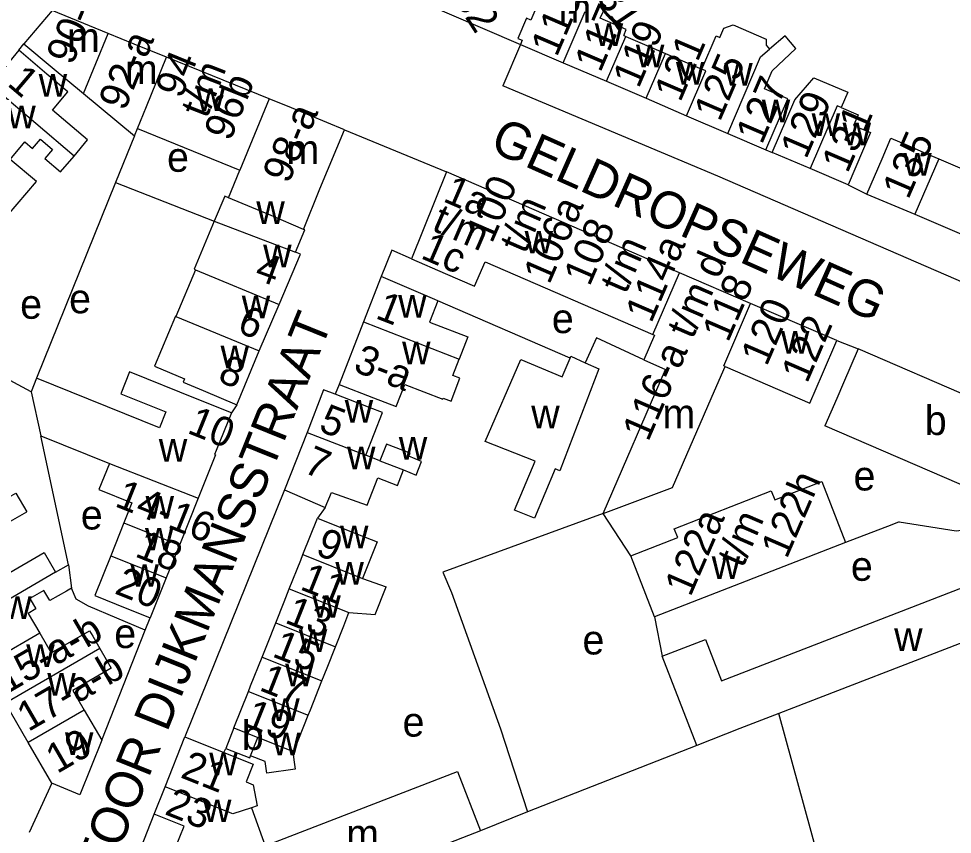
# Model space of a CAD drawing. Extents: x 161141 to 163125, y 381621 to 383200.
# Drawn here: x 162150.7 to 162277.6, y 382532 to 382642.8 of the extents above; entities that cross this region are included whole.
import ezdxf

# ---------------------------------------------------------------- set-up
doc = ezdxf.new("R2010")
doc.units = 0
for name, color, linetype in [('BLT_Basislijn', 7, 'Continuous'), ('BLT_Bebouwing', 7, 'Continuous'), ('BLT_Centroide', 7, 'Continuous'), ('BLT_Huisnummer', 7, 'Continuous'), ('BLT_Huisnummer_ tussenligend', 7, 'Continuous'), ('BLT_Huisnummer_reeks', 7, 'Continuous'), ('BLT_Onderverdeling_panden', 7, 'Continuous'), ('BLT_Straatnaam', 7, 'Continuous'), ('BLT_Vlakafsluiter', 7, 'Continuous')]:
    doc.layers.add(name, color=color, linetype=linetype)

msp = doc.modelspace()

# ---------------------------------------------------------------- linework, layer by layer
at = {"layer": 'BLT_Basislijn'}
for p, q in [((162150.75, 382638.48), (162151.43, 382639.36)), ((162218.92, 382639.28), (162216.51, 382633.67)), ((162166.46, 382626.88), (162163.9, 382620.53)), ((162252.26, 382624.97), (162253.12, 382624.62)), ((162163.9, 382620.53), (162153.17, 382593.92)), ((162163.9, 382620.53), (162177.31, 382615.28)), ((162263.41, 382620.2), (162265.95, 382618.96)), ((162261.9, 382599.06), (162264.79, 382597.91)), ((162194.26, 382593.1), (162193.71, 382591.77)), ((162180.39, 382590.32), (162179.64, 382589.24)), ((162157.52, 382568.57), (162153.72, 382586.1)), ((162186.87, 382578.76), (162173.32, 382545.19)), ((162192.38, 382576.39), (162191.32, 382574.93)), ((162233.91, 382569.8), (162230.16, 382575.56)), ((162270.38, 382574.4), (162269.36, 382574.02)), ((162269.36, 382574.02), (162263.07, 382571.62)), ((162167.92, 382559.68), (162168.6, 382561.4)), ((162237.14, 382561.53), (162238.16, 382556.17)), ((162162.02, 382544.74), (162167.92, 382559.68)), ((162260.76, 382523.75), (162254, 382548.36)), ((162242.85, 382544.04), (162219.85, 382535)), ((162178.61, 382543.09), (162178.88, 382543.64)), ((162155.22, 382538.91), (162152.16, 382532.22)), ((162219.85, 382535), (162213.46, 382532.44))]:
    msp.add_line(p, q, dxfattribs=at)
for points in [[(162377.15, 382570.34), (162374.71, 382570.72), (162341.47, 382580.52), (162303.7, 382596.26), (162245.74, 382621.4), (162216.51, 382633.67)], [(162204.09, 382610.15), (162201.43, 382611.31), (162199.96, 382607.76)], [(162225.64, 382596.66), (162207.69, 382604.46)], [(162235.65, 382596.41), (162229.24, 382599.4), (162227.72, 382596.04)], [(162152.43, 382592.09), (162143.75, 382596.76), (162138.41, 382593.73)], [(162270.38, 382574.4), (162278.09, 382573.22), (162281.73, 382573.67), (162282.87, 382574.53), (162284.03, 382577.2)], [(162230.16, 382575.56), (162208.38, 382567.57), (162209.55, 382564.84), (162216.18, 382546.3), (162219.85, 382535)], [(162167.92, 382559.68), (162160.23, 382562.96), (162158.56, 382563.92), (162157.9, 382565.43)]]:
    msp.add_lwpolyline(points, dxfattribs=at)
at = {"layer": 'BLT_Bebouwing'}
for p, q in [((162155.26, 382643.89), (162151.43, 382639.36)), ((162162.87, 382640.78), (162155.26, 382643.89)), ((162166.4, 382639.34), (162162.87, 382640.78)), ((162232.93, 382640.49), (162233.21, 382640.37)), ((162233.21, 382640.37), (162238.59, 382638.06)), ((162170.81, 382637.55), (162166.4, 382639.34)), ((162218.92, 382639.28), (162224.72, 382636.79)), ((162150.75, 382638.48), (162146.81, 382633.83)), ((162238.59, 382638.06), (162243.56, 382635.93)), ((162184.76, 382631.9), (162170.81, 382637.55)), ((162224.72, 382636.79), (162230.59, 382634.27)), ((162230.59, 382634.27), (162235.97, 382631.96)), ((162159.55, 382632.63), (162166.46, 382626.88)), ((162187.8, 382630.65), (162184.76, 382631.9)), ((162235.97, 382631.96), (162241.48, 382629.59)), ((162194.98, 382627.7), (162187.8, 382630.65)), ((162241.48, 382629.59), (162247.06, 382627.2)), ((162166.46, 382626.88), (162166.86, 382627.87)), ((162191.67, 382619.65), (162194.98, 382627.7)), ((162247.06, 382627.2), (162252.26, 382624.97)), ((162258.27, 382622.41), (162253.12, 382624.62)), ((162275.73, 382623.74), (162282.08, 382621.01)), ((162179.23, 382618.46), (162180.77, 382622.2)), ((162208.85, 382621.96), (162204.09, 382610.15)), ((162240.52, 382608.24), (162208.85, 382621.96)), ((162263.41, 382620.2), (162258.27, 382622.41)), ((162189.41, 382614.16), (162191.67, 382619.65)), ((162265.95, 382618.96), (162272.48, 382616.2)), ((162272.48, 382616.2), (162278.85, 382613.51)), ((162174.76, 382608.68), (162172.09, 382602.33)), ((162199.96, 382607.76), (162197.56, 382601.59)), ((162250.18, 382604.08), (162240.52, 382608.24)), ((162183.4, 382597.64), (162186.12, 382603.97)), ((162261.9, 382599.06), (162250.18, 382604.08)), ((162197.56, 382601.59), (162194.26, 382593.1)), ((162180.39, 382590.32), (162183.4, 382597.64)), ((162288.54, 382587.63), (162264.79, 382597.91)), ((162235.65, 382596.41), (162238.62, 382595.12)), ((162230.16, 382575.56), (162238.62, 382595.12)), ((162245.28, 382592.24), (162246.71, 382595.54)), ((162246.71, 382595.54), (162258.22, 382590.55)), ((162153.17, 382593.92), (162152.43, 382592.09)), ((162169.86, 382587.21), (162153.17, 382593.92)), ((162239.56, 382579.07), (162245.28, 382592.24)), ((162152.43, 382592.09), (162153.72, 382586.1)), ((162179.64, 382589.24), (162177.58, 382584.11)), ((162284.03, 382577.2), (162260.27, 382587.47)), ((162153.72, 382586.1), (162163.06, 382582.34)), ((162189.91, 382586.57), (162186.87, 382578.76)), ((162186.87, 382578.76), (162192.38, 382576.39)), ((162230.16, 382575.56), (162239.56, 382579.07)), ((162175.12, 382577.62), (162172.56, 382571.27)), ((162148.68, 382573.96), (162151.82, 382575.78)), ((162189.35, 382569.97), (162191.32, 382574.93)), ((162165.03, 382574.3), (162163.23, 382569.82)), ((162172.56, 382571.27), (162170.77, 382566.79)), ((162263.07, 382571.62), (162237.14, 382561.53)), ((162148.98, 382567.24), (162154.19, 382570.26)), ((162154.19, 382570.26), (162155.75, 382567.56)), ((162189.05, 382569.23), (162189.35, 382569.97)), ((162237.14, 382561.53), (162233.91, 382569.8)), ((162155.75, 382567.56), (162157.52, 382568.57)), ((162157.52, 382568.57), (162157.9, 382565.43)), ((162187.5, 382565.32), (162189.05, 382569.23)), ((162170.77, 382566.79), (162168.6, 382561.4)), ((162246.2, 382552.82), (162282.68, 382566.95)), ((162197.46, 382566.74), (162200.68, 382565.57)), ((162186.79, 382563.53), (162187.5, 382565.32)), ((162185.65, 382560.68), (162186.79, 382563.53)), ((162194.9, 382560.3), (162195.61, 382562.1)), ((162184.52, 382557.83), (162185.65, 382560.68)), ((162285.2, 382560.44), (162254, 382548.36)), ((162193.76, 382557.45), (162194.9, 382560.3)), ((162238.16, 382556.17), (162244.03, 382558.44)), ((162244.03, 382558.44), (162246.2, 382552.82)), ((162183.8, 382556.03), (162184.52, 382557.83)), ((162192.63, 382554.6), (162193.76, 382557.45)), ((162182.25, 382552.13), (162183.8, 382556.03)), ((162242.85, 382544.04), (162238.16, 382556.17)), ((162191.92, 382552.8), (162192.63, 382554.6)), ((162190.36, 382548.9), (162191.92, 382552.8)), ((162181.96, 382551.39), (162182.25, 382552.13)), ((162179.98, 382546.43), (162181.96, 382551.39)), ((162152.02, 382544.43), (162148.93, 382549.77)), ((162159.64, 382548.85), (162162.02, 382544.74)), ((162190.07, 382548.16), (162190.36, 382548.9)), ((162254, 382548.36), (162248.72, 382546.32)), ((162170.63, 382538.43), (162173.32, 382545.19)), ((162173.32, 382545.19), (162178.61, 382543.09)), ((162248.72, 382546.32), (162242.85, 382544.04)), ((162155.22, 382538.91), (162152.02, 382544.43)), ((162178.61, 382543.09), (162182.61, 382541.5)), ((162169.14, 382534.69), (162170.63, 382538.43)), ((162165.28, 382524.99), (162169.14, 382534.69))]:
    msp.add_line(p, q, dxfattribs=at)
for points in [[(162221.87, 382646.21), (162220.32, 382642.6), (162219.72, 382642.85), (162218.54, 382640.1), (162219.16, 382639.84), (162218.92, 382639.28)], [(162232.93, 382640.49), (162233.27, 382641.32), (162229.74, 382642.83), (162230.49, 382644.49), (162229.91, 382644.87)], [(162246, 382640.21), (162246.54, 382641.47), (162247.79, 382641.95), (162252.31, 382640.01), (162252.28, 382639.18), (162252.75, 382638.63)], [(162243.56, 382635.93), (162245.49, 382640.43), (162246, 382640.21)], [(162252.26, 382624.97), (162254.23, 382629.56), (162255.22, 382631.89), (162252.05, 382633.24), (162253.1, 382635.69), (162256.33, 382638.73), (162254.89, 382640.44), (162252.75, 382638.63)], [(162151.43, 382639.36), (162155.28, 382636.17), (162159.55, 382632.63)], [(162158.25, 382624.12), (162160.09, 382626.3), (162155.33, 382630.34), (162157.43, 382632.82), (162154.55, 382635.26), (162150.75, 382638.48)], [(162253.12, 382624.62), (162255.09, 382629.22), (162256.18, 382631.75), (162258.75, 382634.76), (162263.38, 382632.78), (162262.49, 382630.71)], [(162262.49, 382630.71), (162264.78, 382629.73), (162264.15, 382628.27), (162266.46, 382627.31), (162265.38, 382624.8), (162263.41, 382620.2)], [(162166.86, 382627.87), (162180.77, 382622.2)], [(162149.56, 382623.64), (162151.59, 382626.04), (162152.61, 382625.14), (162153.68, 382626.41), (162155.33, 382625.02), (162154.27, 382623.77), (162156.41, 382621.95), (162158.25, 382624.12)], [(162265.95, 382618.96), (162268.05, 382623.75), (162269.24, 382626.53), (162271.56, 382625.53), (162274.14, 382624.42), (162275.73, 382623.74)], [(162148.93, 382616.29), (162149.21, 382616.05), (162153.14, 382620.66), (162149.56, 382623.64)], [(162179.23, 382618.46), (162178.74, 382618.67), (162177.31, 382615.28)], [(162177.31, 382615.28), (162174.56, 382608.77), (162174.76, 382608.68)], [(162188.35, 382611.06), (162189.62, 382614.07), (162189.41, 382614.16)], [(162186.12, 382603.97), (162189, 382610.79), (162188.35, 382611.06)], [(162204.09, 382610.15), (162208.68, 382608.16), (162212.68, 382606.43), (162214.11, 382609.73), (162236.89, 382599.85)], [(162207.69, 382604.46), (162207.26, 382604.64), (162199.96, 382607.76)], [(162207.69, 382604.46), (162206.56, 382601.56), (162211.75, 382599.54), (162210.58, 382596.53)], [(162172.09, 382602.33), (162172.02, 382602.36), (162169.19, 382595.55), (162173.27, 382593.86), (162173.08, 382593.41), (162175.79, 382592.27), (162180.39, 382590.32)], [(162236.89, 382599.85), (162237.1, 382599.76), (162235.65, 382596.41)], [(162258.22, 382590.55), (162259.95, 382594.54), (162261.9, 382599.06)], [(162264.79, 382597.91), (162262.8, 382593.32), (162261.88, 382591.19), (162260.27, 382587.47)], [(162194.26, 382593.1), (162198.92, 382591.28), (162202.02, 382590.08), (162203.18, 382593.09), (162208.37, 382591.08), (162208.42, 382591.2), (162209.47, 382590.8), (162210.68, 382593.93), (162209.71, 382594.31), (162210.58, 382596.53)], [(162227.72, 382596.04), (162229.56, 382595.22), (162224.24, 382581.36), (162223.6, 382581.61), (162220.8, 382574.94), (162218.11, 382575.99), (162220.91, 382582.67), (162214.12, 382585.34), (162218.95, 382596.49), (162224.58, 382594.14), (162225.64, 382596.66)], [(162225.64, 382596.66), (162225.75, 382596.93), (162227.72, 382596.04)], [(162179.64, 382589.24), (162175, 382591.1), (162165.81, 382594.8), (162164.62, 382591.83), (162170.73, 382589.38), (162169.86, 382587.21)], [(162193.71, 382591.77), (162192.16, 382592.37), (162189.91, 382586.57)], [(162197.91, 382583.47), (162200.16, 382589.26), (162198.47, 382589.92), (162193.71, 382591.77)], [(162203.02, 382581.47), (162204.75, 382580.76), (162205.48, 382582.64), (162203.74, 382583.32), (162203.9, 382583.74), (162200.7, 382584.98), (162199.81, 382582.71)], [(162177.58, 382584.11), (162177.35, 382583.56), (162177.49, 382583.51), (162175.12, 382577.62)], [(162199.81, 382582.71), (162197.91, 382583.47)], [(162163.06, 382582.34), (162161.64, 382578.81), (162166.12, 382577.01), (162165.03, 382574.3)], [(162192.38, 382576.39), (162193.24, 382578.39), (162198.07, 382576.67), (162199.51, 382580.38), (162202.18, 382579.34), (162203.02, 382581.47)], [(162233.91, 382569.8), (162240.27, 382572.28), (162239.8, 382573.48), (162252.99, 382578.62), (162253.46, 382577.42), (162259.84, 382579.91), (162259.84, 382579.91), (162263.07, 382571.62)], [(162148.43, 382577.21), (162150.35, 382578.32), (162151.82, 382575.78)], [(162191.32, 382574.93), (162195.97, 382573.08), (162199.43, 382571.7), (162197.46, 382566.74)], [(162163.23, 382569.82), (162161.06, 382564.43), (162163.99, 382563.25), (162168.6, 382561.4)], [(162195.61, 382562.1), (162199.18, 382561.81), (162200.68, 382565.57)], [(162157.9, 382565.43), (162157.24, 382564.99), (162154.96, 382563.72), (162154.15, 382565.11), (162152.26, 382564.01), (162153.08, 382562.58), (162152.03, 382561.97), (162153.59, 382559.29)], [(162153.59, 382559.29), (162155.14, 382556.61), (162160.35, 382559.62), (162160.79, 382558.87), (162161.76, 382557.2)], [(162161.76, 382557.2), (162163.3, 382554.53), (162158.09, 382551.52), (162159.64, 382548.85)], [(162187.93, 382543.4), (162188.19, 382543.43), (162190.07, 382548.16)], [(162179.98, 382546.43), (162178.88, 382543.64)], [(162162.02, 382544.74), (162159.05, 382537.33), (162155.22, 382538.91)], [(162178.88, 382543.64), (162182.13, 382542.35), (162182.24, 382542.63)], [(162187.93, 382543.4), (162188.3, 382540.83), (162184.44, 382540.27), (162184.21, 382541.84), (162182.24, 382542.63)], [(162182.61, 382541.5), (162181.65, 382539.08), (162182.58, 382538.71), (162183.15, 382535.82), (162182.35, 382535.57)], [(162184.23, 382530.38), (162210.34, 382540.49), (162213.46, 382532.44)], [(162182.35, 382535.57), (162184.23, 382530.38)], [(162213.46, 382532.44), (162180.31, 382519.52)]]:
    msp.add_lwpolyline(points, dxfattribs=at)
at = {"layer": 'BLT_Onderverdeling_panden'}
for p, q in [((162224.72, 382636.79), (162227.72, 382643.77)), ((162159.55, 382632.63), (162162.87, 382640.78)), ((162230.59, 382634.27), (162233.21, 382640.37)), ((162235.97, 382631.96), (162238.59, 382638.06)), ((162168.09, 382630.87), (162170.81, 382637.55)), ((162158.25, 382624.12), (162146.81, 382633.83)), ((162184.76, 382631.9), (162180.77, 382622.2)), ((162166.86, 382627.87), (162168.09, 382630.87)), ((162275.73, 382623.74), (162272.48, 382616.2)), ((162177.31, 382615.28), (162188.35, 382611.06)), ((162174.76, 382608.68), (162186.12, 382603.97)), ((162236.89, 382599.85), (162240.52, 382608.24)), ((162172.09, 382602.33), (162183.4, 382597.64)), ((162197.56, 382601.59), (162210.58, 382596.53)), ((162189.91, 382586.57), (162197.91, 382583.47)), ((162163.06, 382582.34), (162175.12, 382577.62)), ((162199.81, 382582.71), (162203.02, 382581.47)), ((162165.03, 382574.3), (162172.56, 382571.27)), ((162163.23, 382569.82), (162170.77, 382566.79)), ((162189.35, 382569.97), (162197.46, 382566.74)), ((162155.75, 382567.56), (162142.93, 382560.13)), ((162187.5, 382565.32), (162195.61, 382562.1)), ((162185.65, 382560.68), (162193.76, 382557.45)), ((162153.59, 382559.29), (162145.97, 382554.88)), ((162161.76, 382557.2), (162148.93, 382549.77)), ((162183.8, 382556.03), (162191.92, 382552.8)), ((162181.96, 382551.39), (162190.07, 382548.16)), ((162159.64, 382548.85), (162152.02, 382544.43)), ((162182.24, 382542.63), (162183.24, 382545.13))]:
    msp.add_line(p, q, dxfattribs=at)
for points in [[(162247.06, 382627.2), (162251.52, 382637.59), (162252.75, 382638.63)], [(162241.48, 382629.59), (162244.1, 382635.7), (162243.56, 382635.93)], [(162262.49, 382630.71), (162261.93, 382630.95), (162258.27, 382622.41)], [(162189.41, 382614.16), (162185.02, 382616.02), (162179.23, 382618.46)], [(162246.71, 382595.54), (162246.52, 382595.62), (162250.18, 382604.08)], [(162179.98, 382546.43), (162183.24, 382545.13)], [(162183.24, 382545.13), (162183.73, 382544.94), (162187.69, 382543.36), (162187.93, 382543.4)], [(162182.35, 382535.57), (162179.82, 382534.77), (162170.63, 382538.43)], [(162184.23, 382530.38), (162178.91, 382528.31), (162175.42, 382529.7), (162175.13, 382528.97), (162172.06, 382530.19), (162173.2, 382533.07), (162169.14, 382534.69)]]:
    msp.add_lwpolyline(points, dxfattribs=at)
at = {"layer": 'BLT_Vlakafsluiter'}
for p, q in [((162199.84, 382647.5), (162218.92, 382639.28)), ((162194.98, 382627.7), (162208.85, 382621.96))]:
    msp.add_line(p, q, dxfattribs=at)

# ---------------------------------------------------------------- texts
at = {"layer": 'BLT_Centroide'}
for s, p in [('m', (162224.09, 382642.22)), ('w', (162229, 382639.08)), ('m', (162157.3, 382638.25)), ('w', (162234.59, 382636.17)), ('m', (162165.17, 382633.89)), ('w', (162240.03, 382633.83)), ('w', (162246.59, 382633.69)), ('w', (162153.45, 382632.19)), ('w', (162174.87, 382630.25)), ('w', (162251.69, 382628.72)), ('w', (162149.18, 382627.88)), ('w', (162258.47, 382626.83)), ('w', (162262.67, 382625.58)), ('e', (162170.89, 382621.98)), ('m', (162187.11, 382623.03)), ('w', (162270.91, 382621.45)), ('w', (162183.02, 382614.88)), ('w', (162219.47, 382610.88)), ('w', (162183.95, 382609)), ('e', (162150.93, 382602.01)), ('e', (162157.58, 382602.75)), ('w', (162181.04, 382602.09)), ('w', (162202.29, 382602.16)), ('e', (162223.17, 382600.06)), ('w', (162254.3, 382597.28)), ('w', (162202.82, 382595.84)), ('w', (162178.16, 382595.28)), ('w', (162195.03, 382587.91)), ('w', (162220.37, 382587.12)), ('m', (162238.2, 382587.11)), ('b', (162273.84, 382586.22)), ('w', (162202.38, 382582.88)), ('w', (162169.77, 382582.59)), ('w', (162195.34, 382581.56)), ('e', (162264.16, 382578.68)), ('w', (162167.97, 382574.84)), ('e', (162159.17, 382573.38)), ('w', (162167.89, 382570.53)), ('w', (162194.39, 382570.84)), ('w', (162244.89, 382566.67)), ('e', (162263.8, 382566.41)), ('w', (162165.91, 382565.59)), ('w', (162193.76, 382565.88)), ('w', (162148.64, 382561.22)), ('w', (162190.63, 382561.38)), ('e', (162163.72, 382557.27)), ('w', (162188.79, 382556.75)), ('e', (162227.33, 382556.4)), ('w', (162269.68, 382556.88)), ('w', (162151.76, 382554.69)), ('w', (162186.93, 382552.09)), ('w', (162154.62, 382550.81)), ('w', (162185.05, 382547.38)), ('e', (162202.89, 382545.24)), ('b', (162181.05, 382543.44)), ('w', (162157.02, 382542.75)), ('w', (162185.15, 382542.69)), ('w', (162176.62, 382539.97)), ('w', (162175.78, 382533.62)), ('m', (162195.23, 382530.03))]:
    msp.add_text(s, height=4, dxfattribs=at).set_placement(p)
at = {"layer": 'BLT_Huisnummer'}
for s, rotation, p in [('119', 66.7685, (162234.96, 382633.19)), ('125', 66.7623, (162246, 382628.66)), ('1', 319.6961, (162149.03, 382633.8)), ('129', 66.8033, (162257.73, 382623.58)), ('135', 66.7677, (162271.6, 382618.09)), ('1', 338.7661, (162199.06, 382602.13)), ('6', 337.0879, (162180.24, 382600.29)), ('10', 338.0886, (162173.48, 382586.55)), ('5', 338.7731, (162191.33, 382586.82)), ('7', 336.7914, (162189.25, 382581.23)), ('9', 338.3046, (162190.91, 382570.02)), ('20', 338.0956, (162163.61, 382564.74)), ('13', 338.3107, (162186.75, 382560.76)), ('17', 338.3107, (162183.27, 382551.59)), ('19', 338.3107, (162181.22, 382546.74)), ('19', 30.093, (162155.95, 382540.14)), ('21', 338.3071, (162172.56, 382539.74))]:
    msp.add_text(s, height=4, rotation=rotation, dxfattribs=at).set_placement(p)
at = {"layer": 'BLT_Huisnummer_ tussenligend'}
for s, rotation, p in [('117', 66.7661, (162229.76, 382635.35)), ('121', 66.7685, (162240.62, 382631.32)), ('127', 66.7623, (162251.7, 382625.56)), ('131', 66.8033, (162263.35, 382621.66)), ('4', 339.8022, (162182.62, 382607.45)), ('8', 337.0879, (162177.61, 382593.59)), ('18', 338.0956, (162166.37, 382569.77)), ('11', 338.3046, (162188.8, 382565.29)), ('15', 338.3107, (162185.03, 382556.17)), ('23', 338.3071, (162170.42, 382534.74))]:
    msp.add_text(s, height=4, rotation=rotation, dxfattribs=at).set_placement(p)
at = {"layer": 'BLT_Huisnummer_reeks'}
for s, rotation, p in [('202a t/m 232', 302.7077, (162196.01, 382666.83)), ('231', 303.9446, (162227.44, 382648.22)), ('90-a', 67.8386, (162158.03, 382636.33)), ('115', 66.7658, (162223.84, 382637.46)), ('92-a', 67.8349, (162165.15, 382630.11)), ('94', 67.8368, (162172.85, 382631.79)), ('t/m', 68.768, (162176.31, 382629.11)), ('96b', 68.019, (162179.48, 382626)), ('98-a', 67.6499, (162187.42, 382620.22)), ('100', 66.5663, (162215.03, 382612.12)), ('1a', 336.6526, (162208.23, 382618.02)), ('t/m', 66.5681, (162219.57, 382610.7)), ('106a', 66.5747, (162222.82, 382606.55)), ('t/m', 336.6526, (162206.69, 382614.09)), ('108', 66.5681, (162228.29, 382606.29)), ('1c', 336.5727, (162205.2, 382610.29)), ('t/m', 66.5681, (162233.21, 382605.23)), ('114a', 66.5663, (162236.67, 382601.29)), ('116-a t/m d', 66.5681, (162236.26, 382585.19)), ('118', 66.5681, (162247.11, 382598.68)), ('120', 66.5765, (162252.36, 382595.43)), ('122', 66.5765, (162257.85, 382593.11)), ('3-a', 338.7718, (162196.03, 382594.95)), ('122h', 66.6064, (162255.09, 382569.27)), ('14-16', 338.0939, (162163.64, 382576.59)), ('122a', 66.6064, (162242, 382564.11)), ('t/m', 66.6064, (162249.12, 382568.03)), ('15-a-b', 30.0733, (162149.08, 382550.95)), ('17-a-b', 30.0733, (162152.03, 382545.84))]:
    msp.add_text(s, height=4, rotation=rotation, dxfattribs=at).set_placement(p)
at = {"layer": 'BLT_Straatnaam'}
for s, rotation, p in [('GELDROPSEWEG', 335.9765, (162214.55, 382624.93)), ('PASTOOR DIJKMANSSTRAAT', 68.0555, (162157.97, 382513.69))]:
    msp.add_text(s, height=5, rotation=rotation, dxfattribs=at).set_placement(p)

doc.saveas('drawing.dxf')
